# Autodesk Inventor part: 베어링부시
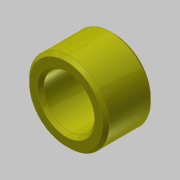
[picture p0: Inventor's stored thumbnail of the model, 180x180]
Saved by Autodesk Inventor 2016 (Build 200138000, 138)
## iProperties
Created: 2019-03
Part Number: 베어링부시
Material: 강철, 연강
Document SubType Name: Modeling
Designer: mduedu
Density: 1 g/cm^3
Appearance: 노란색
Author: mduedu
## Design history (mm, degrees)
sketch "스케치1"
  geometry: L1 (-7.5, 12.5)-(7.5, 12.5); L2 (7.5, 12.5)-(7.5, 8); L3 (7.5, 8)-(-7.5, 8); L4 (-7.5, 8)-(-7.5, 12.5); L5 (-7.5, 0)-(7.5, 0); 3 further points
  constraints: 10 end point, 2 midpoint, 2 parallel, 2 perpendicular, 2 vertical alignment, 1 coincident, 1 horizontal
  dimensions: "d0" = 16 diameter of L3 L5; "d2" = 25 diameter of L1 L5; "d3" = 15 distance of L1.start L1.end
revolve "회전1" sketch "스케치1" stored, may be unused: angle "d4" = 90 deg
chamfer "모따기1" distance "d5" = 1; stored, may be unused: second distance "d6" = 2, angle "d7" = 45 deg
chamfer "모따기2" distance "d8" = 1; stored, may be unused: second distance "d9" = 2, angle "d10" = 45 deg
node "솔리드1"
